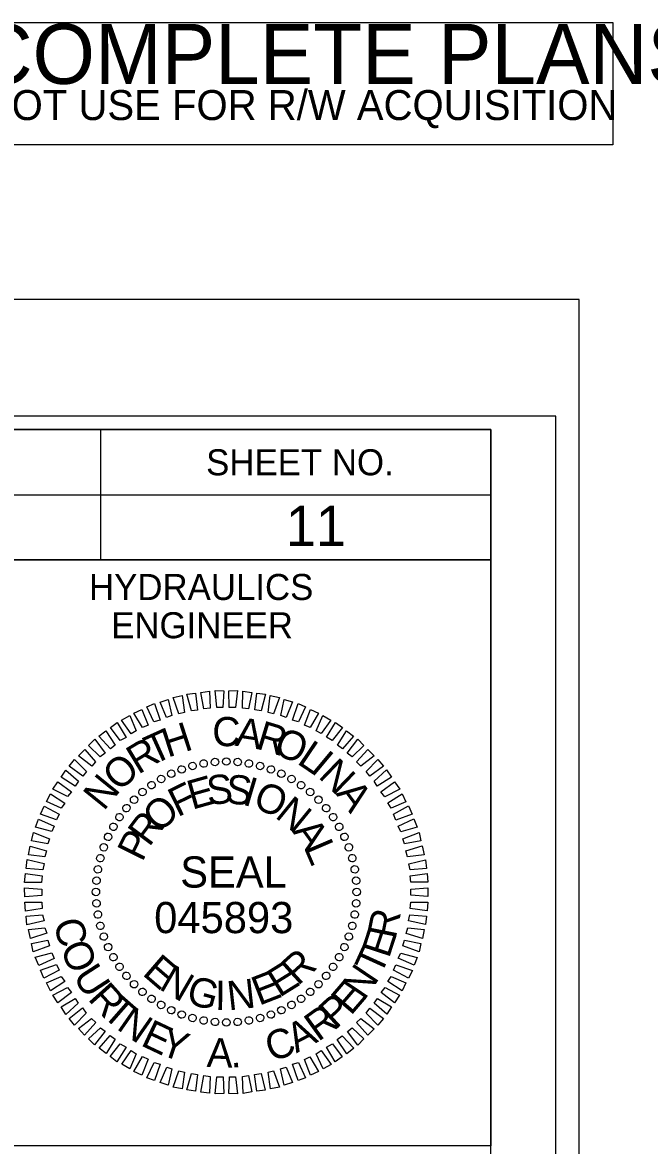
# Model space of a CAD drawing. Extents: x 1621288 to 1629363, y 896995 to 899414.
# Drawn here: x 1628879.4 to 1628999.9, y 897932.1 to 898147.8 of the extents above; entities that cross this region are included whole.
import ezdxf

# ---------------------------------------------------------------- set-up
doc = ezdxf.new("R2010")
doc.units = 0
for name, color, linetype in [('Default', 7, 'Continuous'), ('Exist XS Ground Line', 7, 'Continuous'), ('Prop Plan Preparation Cover Label', 7, 'Continuous'), ('Prop Vertical Profile Curve Label', 7, 'Continuous'), ('Prop Vertical Profile Grade Label', 7, 'Continuous'), ('Sheet Layout Plan Border', 7, 'Continuous'), ('Sheet Layout Profile Border', 7, 'Continuous')]:
    doc.layers.add(name, color=color, linetype=linetype)

msp = doc.modelspace()

# ---------------------------------------------------------------- linework, layer by layer
at = {"layer": 'Default'}
for p, q in [((1628912.06, 898005.01), (1628912.06, 898005.01)), ((1628914.21, 898005.46), (1628914.21, 898005.46)), ((1628916.36, 898005.76), (1628916.36, 898005.76)), ((1628918.56, 898005.91), (1628918.56, 898005.91)), ((1628920.76, 898005.76), (1628920.76, 898005.76)), ((1628922.91, 898005.46), (1628922.91, 898005.46)), ((1628925.06, 898005.01), (1628925.06, 898005.01)), ((1628906.06, 898002.51), (1628906.06, 898002.51)), ((1628908.01, 898003.51), (1628908.01, 898003.51)), ((1628909.96, 898004.36), (1628909.96, 898004.36)), ((1628927.16, 898004.36), (1628927.16, 898004.36)), ((1628929.16, 898003.51), (1628929.16, 898003.51)), ((1628931.11, 898002.51), (1628931.11, 898002.51)), ((1628904.21, 898001.31), (1628904.21, 898001.31)), ((1628932.91, 898001.36), (1628932.91, 898001.36)), ((1628900.81, 897998.51), (1628900.81, 897998.51)), ((1628902.41, 898000.06), (1628902.41, 898000.06)), ((1628934.71, 898000.01), (1628934.71, 898000.01)), ((1628936.26, 897998.56), (1628936.26, 897998.56)), ((1628899.31, 897996.96), (1628899.31, 897996.96)), ((1628937.81, 897996.91), (1628937.81, 897996.91)), ((1628898.01, 897995.16), (1628898.01, 897995.16)), ((1628939.06, 897995.16), (1628939.06, 897995.16)), ((1628896.81, 897993.31), (1628896.81, 897993.31)), ((1628940.26, 897993.31), (1628940.26, 897993.31)), ((1628894.96, 897989.36), (1628894.96, 897989.36)), ((1628895.81, 897991.36), (1628895.81, 897991.36)), ((1628941.26, 897991.36), (1628941.26, 897991.36)), ((1628942.11, 897989.36), (1628942.11, 897989.36)), ((1628894.31, 897987.31), (1628894.31, 897987.31)), ((1628942.76, 897987.31), (1628942.76, 897987.31)), ((1628893.86, 897985.16), (1628893.86, 897985.16)), ((1628943.21, 897985.11), (1628943.21, 897985.11)), ((1628893.56, 897983.01), (1628893.56, 897983.01)), ((1628943.51, 897982.96), (1628943.51, 897982.96)), ((1628893.46, 897980.81), (1628893.46, 897980.81)), ((1628943.66, 897980.76), (1628943.66, 897980.76)), ((1628893.61, 897978.61), (1628893.61, 897978.61)), ((1628943.56, 897978.56), (1628943.56, 897978.56)), ((1628893.91, 897976.46), (1628893.91, 897976.46)), ((1628943.26, 897976.46), (1628943.26, 897976.46)), ((1628894.36, 897974.31), (1628894.36, 897974.31)), ((1628942.76, 897974.26), (1628942.76, 897974.26)), ((1628895.01, 897972.21), (1628895.01, 897972.21)), ((1628942.11, 897972.21), (1628942.11, 897972.21)), ((1628895.86, 897970.21), (1628895.86, 897970.21)), ((1628941.31, 897970.21), (1628941.31, 897970.21)), ((1628896.86, 897968.26), (1628896.86, 897968.26)), ((1628940.31, 897968.26), (1628940.31, 897968.26)), ((1628898.06, 897966.41), (1628898.06, 897966.41)), ((1628939.11, 897966.41), (1628939.11, 897966.41)), ((1628899.31, 897964.66), (1628899.31, 897964.66)), ((1628937.76, 897964.66), (1628937.76, 897964.66)), ((1628900.81, 897963.06), (1628900.81, 897963.06)), ((1628902.41, 897961.56), (1628902.41, 897961.56)), ((1628934.66, 897961.56), (1628934.66, 897961.56)), ((1628936.31, 897963.06), (1628936.31, 897963.06)), ((1628904.16, 897960.26), (1628904.16, 897960.26)), ((1628932.91, 897960.31), (1628932.91, 897960.31)), ((1628906.01, 897959.06), (1628906.01, 897959.06)), ((1628907.96, 897958.06), (1628907.96, 897958.06)), ((1628909.96, 897957.21), (1628909.96, 897957.21)), ((1628927.11, 897957.21), (1628927.11, 897957.21)), ((1628929.11, 897958.06), (1628929.11, 897958.06)), ((1628931.11, 897959.06), (1628931.11, 897959.06)), ((1628912.06, 897956.56), (1628912.06, 897956.56)), ((1628914.21, 897956.11), (1628914.21, 897956.11)), ((1628916.36, 897955.81), (1628916.36, 897955.81)), ((1628918.51, 897955.71), (1628918.51, 897955.71)), ((1628920.71, 897955.86), (1628920.71, 897955.86)), ((1628922.91, 897956.11), (1628922.91, 897956.11)), ((1628925.06, 897956.56), (1628925.06, 897956.56))]:
    msp.add_line(p, q, dxfattribs=at)
for points in [[(1628916.76, 898016.26), (1628916.41, 898019.51), (1628918.06, 898019.46), (1628917.91, 898016.26)], [(1628919.11, 898016.26), (1628919.06, 898019.46), (1628920.71, 898019.51), (1628920.31, 898016.26)], [(1628907.06, 898014.36), (1628905.86, 898017.31), (1628907.41, 898017.81), (1628908.11, 898014.71)], [(1628909.46, 898015.06), (1628908.36, 898018.21), (1628910.06, 898018.56), (1628910.51, 898015.31)], [(1628911.86, 898015.66), (1628911.01, 898018.81), (1628912.66, 898019.01), (1628913.06, 898015.76)], [(1628914.26, 898016.01), (1628913.66, 898019.16), (1628915.31, 898019.41), (1628915.46, 898016.16)], [(1628921.66, 898016.16), (1628921.76, 898019.41), (1628923.46, 898019.16), (1628922.86, 898016.01)], [(1628924.06, 898015.81), (1628924.46, 898019.01), (1628926.11, 898018.81), (1628925.26, 898015.66)], [(1628926.61, 898015.31), (1628927.01, 898018.56), (1628928.76, 898018.21), (1628927.66, 898015.06)], [(1628929.01, 898014.71), (1628929.66, 898017.81), (1628931.26, 898017.36), (1628930.06, 898014.36)], [(1628902.46, 898012.41), (1628900.81, 898015.21), (1628902.36, 898015.91), (1628903.56, 898012.91)], [(1628904.66, 898013.51), (1628903.31, 898016.41), (1628904.76, 898017.01), (1628905.86, 898013.86)], [(1628931.26, 898013.86), (1628932.36, 898017.01), (1628933.81, 898016.41), (1628932.41, 898013.51)], [(1628933.56, 898012.91), (1628934.71, 898015.91), (1628936.31, 898015.21), (1628934.66, 898012.41)], [(1628898.16, 898009.91), (1628896.31, 898012.41), (1628897.61, 898013.41), (1628899.31, 898010.51)], [(1628900.31, 898011.21), (1628898.41, 898013.86), (1628900.01, 898014.71), (1628901.26, 898011.81)], [(1628935.81, 898011.81), (1628937.11, 898014.71), (1628938.66, 898013.86), (1628936.81, 898011.26)], [(1628937.81, 898010.56), (1628939.56, 898013.41), (1628940.86, 898012.41), (1628938.91, 898009.91)], [(1628896.31, 898008.36), (1628894.06, 898010.76), (1628895.41, 898011.81), (1628897.21, 898009.06)], [(1628939.91, 898009.06), (1628941.66, 898011.81), (1628943.01, 898010.76), (1628940.86, 898008.36)], [(1628894.31, 898006.81), (1628892.11, 898008.96), (1628893.31, 898010.16), (1628895.26, 898007.51)], [(1628941.81, 898007.51), (1628943.81, 898010.16), (1628945.01, 898008.96), (1628942.76, 898006.81)], [(1628892.71, 898005.01), (1628890.16, 898007.01), (1628891.36, 898008.21), (1628893.46, 898005.81)], [(1628943.61, 898005.81), (1628945.76, 898008.21), (1628946.96, 898007.01), (1628944.41, 898005.01)], [(1628891.01, 898003.11), (1628888.36, 898005.01), (1628889.41, 898006.31), (1628891.71, 898004.01)], [(1628945.41, 898004.01), (1628947.71, 898006.31), (1628948.76, 898005.01), (1628946.11, 898003.06)], [(1628889.51, 898001.16), (1628886.81, 898002.86), (1628887.71, 898004.26), (1628890.16, 898002.11)], [(1628946.96, 898002.11), (1628949.36, 898004.31), (1628950.31, 898002.86), (1628947.56, 898001.16)], [(1628888.06, 897999.16), (1628885.26, 898000.56), (1628886.21, 898002.01), (1628888.81, 898000.06)], [(1628948.26, 898000.06), (1628950.91, 898002.01), (1628951.91, 898000.56), (1628949.01, 897999.11)], [(1628886.86, 897996.96), (1628884.01, 897998.21), (1628884.76, 897999.71), (1628887.51, 897997.91)], [(1628949.61, 897997.96), (1628952.36, 897999.71), (1628953.06, 897998.16), (1628950.21, 897996.96)], [(1628885.96, 897994.71), (1628882.86, 897995.81), (1628883.56, 897997.31), (1628886.46, 897995.76)], [(1628950.66, 897995.81), (1628953.56, 897997.36), (1628954.26, 897995.76), (1628951.16, 897994.66)], [(1628885.01, 897992.46), (1628881.91, 897993.31), (1628882.46, 897994.81), (1628885.51, 897993.46)], [(1628951.61, 897993.51), (1628954.61, 897994.86), (1628955.21, 897993.26), (1628952.11, 897992.41)], [(1628884.26, 897990.06), (1628881.16, 897990.66), (1628881.51, 897992.26), (1628884.61, 897991.06)], [(1628952.46, 897991.06), (1628955.61, 897992.26), (1628955.96, 897990.66), (1628952.81, 897990.06)], [(1628883.71, 897987.61), (1628880.56, 897987.96), (1628880.86, 897989.66), (1628884.01, 897988.71)], [(1628953.06, 897988.71), (1628956.21, 897989.71), (1628956.56, 897987.96), (1628953.41, 897987.61)], [(1628883.31, 897985.11), (1628880.11, 897985.36), (1628880.31, 897987.06), (1628883.56, 897986.31)], [(1628953.61, 897986.26), (1628956.81, 897987.01), (1628957.01, 897985.36), (1628953.86, 897985.11)], [(1628883.06, 897982.66), (1628879.81, 897982.66), (1628879.96, 897984.36), (1628883.16, 897983.91)], [(1628953.91, 897983.91), (1628957.16, 897984.41), (1628957.26, 897982.71), (1628954.01, 897982.71)], [(1628883.11, 897980.16), (1628879.86, 897979.91), (1628879.81, 897981.61), (1628883.11, 897981.36)], [(1628954.01, 897981.41), (1628957.26, 897981.66), (1628957.26, 897979.96), (1628954.01, 897980.21)], [(1628883.16, 897977.66), (1628879.96, 897977.16), (1628879.86, 897978.91), (1628883.11, 897978.86)], [(1628954.01, 897978.91), (1628957.26, 897978.91), (1628957.16, 897977.21), (1628953.91, 897977.66)], [(1628883.56, 897975.31), (1628880.26, 897974.51), (1628880.11, 897976.21), (1628883.26, 897976.46)], [(1628953.81, 897976.46), (1628957.01, 897976.21), (1628956.81, 897974.56), (1628953.56, 897975.31)], [(1628884.06, 897972.91), (1628880.91, 897971.91), (1628880.56, 897973.61), (1628883.71, 897973.96)], [(1628953.46, 897973.96), (1628956.56, 897973.61), (1628956.26, 897971.91), (1628953.11, 897972.86)], [(1628884.61, 897970.51), (1628881.46, 897969.31), (1628881.16, 897970.96), (1628884.26, 897971.56)], [(1628952.81, 897971.56), (1628955.96, 897970.96), (1628955.61, 897969.31), (1628952.46, 897970.51)], [(1628885.51, 897968.06), (1628882.51, 897966.71), (1628881.86, 897968.31), (1628885.01, 897969.16)], [(1628952.11, 897969.11), (1628955.21, 897968.26), (1628954.66, 897966.76), (1628951.61, 897968.11)], [(1628886.46, 897965.81), (1628883.51, 897964.26), (1628882.86, 897965.81), (1628885.96, 897966.91)], [(1628951.16, 897966.86), (1628954.31, 897965.76), (1628953.56, 897964.26), (1628950.66, 897965.81)], [(1628887.51, 897963.66), (1628884.76, 897961.86), (1628884.01, 897963.41), (1628886.86, 897964.61)], [(1628950.26, 897964.61), (1628953.06, 897963.41), (1628952.36, 897961.86), (1628949.61, 897963.66)], [(1628888.81, 897961.56), (1628886.21, 897959.56), (1628885.26, 897961.01), (1628888.06, 897962.46)], [(1628949.06, 897962.46), (1628951.86, 897961.01), (1628950.91, 897959.56), (1628948.31, 897961.56)], [(1628890.11, 897959.46), (1628887.71, 897957.31), (1628886.81, 897958.76), (1628889.51, 897960.41)], [(1628947.61, 897960.41), (1628950.31, 897958.76), (1628949.41, 897957.36), (1628946.96, 897959.46)], [(1628891.66, 897957.56), (1628889.41, 897955.26), (1628888.36, 897956.56), (1628890.96, 897958.56)], [(1628946.11, 897958.51), (1628948.76, 897956.56), (1628947.71, 897955.26), (1628945.41, 897957.56)], [(1628893.51, 897955.76), (1628891.31, 897953.36), (1628890.16, 897954.61), (1628892.66, 897956.56)], [(1628944.41, 897956.56), (1628946.96, 897954.56), (1628945.76, 897953.36), (1628943.61, 897955.76)], [(1628895.31, 897954.11), (1628893.26, 897951.46), (1628892.11, 897952.66), (1628894.36, 897954.76)], [(1628897.21, 897952.56), (1628895.46, 897949.81), (1628894.11, 897950.81), (1628896.26, 897953.26)], [(1628940.81, 897953.21), (1628943.06, 897950.81), (1628941.71, 897949.76), (1628939.86, 897952.51)], [(1628942.76, 897954.76), (1628945.01, 897952.61), (1628943.81, 897951.41), (1628941.86, 897954.06)], [(1628899.31, 897951.06), (1628897.56, 897948.21), (1628896.26, 897949.21), (1628898.16, 897951.66)], [(1628938.96, 897951.66), (1628940.81, 897949.16), (1628939.51, 897948.21), (1628937.81, 897951.06)], [(1628901.26, 897949.76), (1628900.01, 897946.86), (1628898.46, 897947.76), (1628900.31, 897950.36)], [(1628903.56, 897948.71), (1628902.36, 897945.66), (1628900.81, 897946.36), (1628902.46, 897949.21)], [(1628934.61, 897949.16), (1628936.31, 897946.36), (1628934.76, 897945.66), (1628933.56, 897948.66)], [(1628936.76, 897950.36), (1628938.71, 897947.71), (1628937.16, 897946.86), (1628935.86, 897949.76)], [(1628905.86, 897947.76), (1628904.76, 897944.61), (1628903.31, 897945.16), (1628904.71, 897948.11)], [(1628908.11, 897946.86), (1628907.41, 897943.76), (1628905.86, 897944.26), (1628907.11, 897947.21)], [(1628910.51, 897946.26), (1628910.06, 897943.06), (1628908.36, 897943.36), (1628909.46, 897946.51)], [(1628927.66, 897946.51), (1628928.76, 897943.36), (1628927.06, 897943.01), (1628926.61, 897946.26)], [(1628930.06, 897947.21), (1628931.26, 897944.26), (1628929.66, 897943.76), (1628928.96, 897946.86)], [(1628932.41, 897948.11), (1628933.76, 897945.16), (1628932.36, 897944.61), (1628931.26, 897947.76)], [(1628913.06, 897945.81), (1628912.66, 897942.56), (1628911.01, 897942.81), (1628911.86, 897945.96)], [(1628915.46, 897945.41), (1628915.31, 897942.21), (1628913.66, 897942.41), (1628914.26, 897945.56)], [(1628917.96, 897945.36), (1628918.06, 897942.11), (1628916.41, 897942.06), (1628916.76, 897945.31)], [(1628920.36, 897945.31), (1628920.71, 897942.06), (1628919.06, 897942.11), (1628919.16, 897945.36)], [(1628922.81, 897945.56), (1628923.46, 897942.46), (1628921.81, 897942.16), (1628921.66, 897945.41)], [(1628925.26, 897945.96), (1628926.06, 897942.76), (1628924.41, 897942.61), (1628924.01, 897945.76)]]:
    msp.add_lwpolyline(points, close=True, dxfattribs=at)
for centre, major_axis in [((1628916.38, 898005.8), (-0.063, 0.717)), ((1628918.57, 898005.89), (0, 0.719)), ((1628920.75, 898005.8), (0.063, 0.717)), ((1628910, 898004.38), (-0.246, 0.676)), ((1628912.08, 898005.04), (-0.186, 0.695)), ((1628914.21, 898005.51), (-0.125, 0.708)), ((1628922.92, 898005.51), (0.125, 0.708)), ((1628925.05, 898005.04), (0.186, 0.695)), ((1628927.13, 898004.38), (0.246, 0.676)), ((1628906.04, 898002.54), (-0.36, 0.623)), ((1628907.98, 898003.55), (-0.304, 0.652)), ((1628929.15, 898003.55), (0.304, 0.652)), ((1628931.09, 898002.54), (0.36, 0.623)), ((1628902.46, 898000.03), (-0.462, 0.551)), ((1628904.19, 898001.36), (-0.413, 0.589)), ((1628932.94, 898001.36), (0.413, 0.589)), ((1628934.67, 898000.03), (0.462, 0.551)), ((1628900.85, 897998.56), (-0.509, 0.509)), ((1628936.28, 897998.56), (0.509, 0.509)), ((1628898.04, 897995.21), (-0.589, 0.413)), ((1628899.37, 897996.94), (-0.551, 0.462)), ((1628937.76, 897996.94), (0.551, 0.462)), ((1628939.09, 897995.21), (0.589, 0.413)), ((1628896.87, 897993.37), (-0.623, 0.36)), ((1628940.26, 897993.37), (0.623, 0.36)), ((1628895.86, 897991.43), (-0.652, 0.304)), ((1628941.27, 897991.43), (0.652, 0.304)), ((1628895.02, 897989.41), (-0.676, 0.246)), ((1628942.11, 897989.41), (0.676, 0.246)), ((1628894.36, 897987.32), (-0.695, 0.186)), ((1628942.77, 897987.32), (0.695, 0.186)), ((1628893.89, 897985.19), (-0.708, 0.125)), ((1628943.24, 897985.19), (0.708, 0.125)), ((1628893.61, 897983.02), (-0.717, 0.063)), ((1628943.52, 897983.02), (0.717, 0.063)), ((1628893.51, 897980.84), (-0.719, 0)), ((1628943.62, 897980.84), (0.719, 0)), ((1628893.61, 897978.65), (-0.717, -0.063)), ((1628943.52, 897978.65), (0.717, -0.063)), ((1628893.89, 897976.49), (-0.708, -0.125)), ((1628943.24, 897976.49), (0.708, -0.125)), ((1628894.36, 897974.35), (-0.695, -0.186)), ((1628942.77, 897974.35), (0.695, -0.186)), ((1628895.02, 897972.27), (-0.676, -0.246)), ((1628942.11, 897972.27), (0.676, -0.246)), ((1628895.86, 897970.25), (-0.652, -0.304)), ((1628941.27, 897970.25), (0.652, -0.304)), ((1628896.87, 897968.31), (-0.623, -0.36)), ((1628940.26, 897968.31), (0.623, -0.36)), ((1628898.04, 897966.47), (-0.589, -0.413)), ((1628939.09, 897966.47), (0.589, -0.413)), ((1628899.37, 897964.73), (-0.551, -0.462)), ((1628900.85, 897963.12), (-0.509, -0.509)), ((1628936.28, 897963.12), (0.509, -0.509)), ((1628937.76, 897964.73), (0.551, -0.462)), ((1628902.46, 897961.65), (-0.462, -0.551)), ((1628934.67, 897961.65), (0.462, -0.551)), ((1628904.19, 897960.31), (-0.413, -0.589)), ((1628906.04, 897959.14), (-0.36, -0.623)), ((1628931.09, 897959.14), (0.36, -0.623)), ((1628932.94, 897960.31), (0.413, -0.589)), ((1628907.98, 897958.13), (-0.304, -0.652)), ((1628910, 897957.29), (-0.246, -0.676)), ((1628912.08, 897956.64), (-0.186, -0.695)), ((1628914.21, 897956.16), (-0.125, -0.708)), ((1628922.92, 897956.16), (0.125, -0.708)), ((1628925.05, 897956.64), (0.186, -0.695)), ((1628927.13, 897957.29), (0.246, -0.676)), ((1628929.15, 897958.13), (0.304, -0.652)), ((1628916.38, 897955.88), (-0.063, -0.717)), ((1628918.57, 897955.78), (0, -0.719)), ((1628920.75, 897955.88), (0.063, -0.717))]:
    msp.add_ellipse(centre, major_axis=major_axis, ratio=0.999708, dxfattribs=at)
at = {"layer": 'Exist XS Ground Line'}
for p, q in [((1628894.38, 898069.61), (1628894.38, 898044.61)), ((1628769.33, 898057.11), (1628969.38, 898057.11))]:
    msp.add_line(p, q, dxfattribs=at)
for points in [[(1628969.38, 898069.66), (1627469.38, 898069.66), (1627469.38, 897019.66), (1628969.38, 897019.66)], [(1628769.33, 898069.66), (1628969.38, 898069.66), (1628969.38, 898044.61), (1628769.33, 898044.61)], [(1628869.38, 898044.61), (1628969.38, 898044.61), (1628969.38, 897932.11), (1628869.38, 897932.11)]]:
    msp.add_lwpolyline(points, close=True, dxfattribs=at)
at = {"layer": 'Prop Plan Preparation Cover Label'}
msp.add_lwpolyline([(1628845.86, 898124.35), (1628845.86, 898147.85), (1628992.86, 898147.85), (1628992.86, 898124.35)], close=True, dxfattribs=at)
at = {"layer": 'Prop Vertical Profile Curve Label'}
msp.add_lwpolyline([(1627315.38, 897017.11), (1628981.88, 897017.11), (1628981.88, 898072.21), (1627315.38, 898072.21)], close=True, dxfattribs=at)
at = {"layer": 'Sheet Layout Plan Border'}
msp.add_lwpolyline([(1627302.38, 896994.66), (1628986.38, 896994.66), (1628986.38, 898094.66), (1627302.38, 898094.66)], close=True, dxfattribs=at)
at = {"layer": 'Sheet Layout Profile Border'}
msp.add_line((1628986.38, 898094.66), (1627302.38, 898094.66), dxfattribs=at)

# ---------------------------------------------------------------- texts
at = {"layer": 'Default'}
for s, height, rotation, p in [('H', 5.6, 17.9268, (1628907.29, 898006.62)), ('C', 5.6, 359.8514, (1628915.86, 898008.85)), ('A', 5.6, 351.2223, (1628920.1, 898008.95)), ('R', 5.6, 343.1874, (1628924.03, 898008.46)), ('T', 5.6, 24.3275, (1628904.48, 898005.2)), ('O', 5.6, 336.242, (1628927.33, 898007.6)), ('R', 5.6, 31.2729, (1628901.63, 898003.31)), ('L', 5.6, 326.0282, (1628931.95, 898005.62)), ('O', 5.6, 41.4867, (1628897.91, 897999.95)), ('I', 5.6, 320.0485, (1628934.46, 898004.1)), ('N', 5.6, 316.0496, (1628936.05, 898002.93)), ('N', 5.6, 51.032, (1628895.02, 897996.25)), ('E', 5.6, 15.6529, (1628911.99, 897996.61)), ('S', 5.6, 5.0487, (1628915.01, 897997.55)), ('S', 5.6, 354.1866, (1628918.24, 897997.93)), ('I', 5.6, 343.3245, (1628921.47, 897997.69)), ('F', 5.6, 26.1465, (1628909.22, 897995.14)), ('O', 5.6, 336.6634, (1628923.41, 897997.24)), ('A', 5.6, 306.5043, (1628939.48, 897999.73)), ('O', 5.6, 42.0574, (1628905.64, 897992.02)), ('N', 5.6, 320.7526, (1628927.74, 897995.29)), ('R', 5.6, 53.1038, (1628903.73, 897989.33)), ('A', 5.6, 305.8367, (1628931.16, 897992.45)), ('P', 5.6, 63.7079, (1628902.41, 897986.45)), ('L', 5.6, 293.1688, (1628933.41, 897989.41)), ('SEAL', 5.992, 360, (1628909.71, 897981.68)), ('045893', 5.994, 360, (1628904.7, 897972.93)), ('R', 5.6, 78.5969, (1628951.09, 897971.65)), ('C', 5.6, 284.0401, (1628885.33, 897975.08)), ('E', 5.6, 71.9487, (1628949.81, 897967.95)), ('O', 5.6, 292.6692, (1628886.56, 897970.15)), ('T', 5.6, 65.548, (1628948.18, 897964.55)), ('E', 5.6, 319.2324, (1628902.24, 897965.03)), ('R', 5.6, 42.4535, (1628932.31, 897962.69)), ('U', 5.6, 302.883, (1628888.95, 897964.64)), ('N', 5.6, 329.8366, (1628905.42, 897962.29)), ('E', 5.6, 21.2452, (1628924.84, 897958.95)), ('E', 5.6, 31.8494, (1628928.75, 897960.47)), ('N', 5.6, 56.0027, (1628945.08, 897959.87)), ('R', 5.6, 311.7969, (1628891.81, 897960.24)), ('G', 5.6, 344.7525, (1628910.63, 897959.52)), ('I', 5.6, 359.6683, (1628916.37, 897958.19)), ('N', 5.6, 6.3293, (1628919.01, 897958.08)), ('E', 5.6, 49.3544, (1628942.48, 897956.94)), ('T', 5.6, 318.7423, (1628894.49, 897957.16)), ('P', 5.6, 42.7062, (1628939.56, 897954.34)), ('N', 5.6, 325.143, (1628897.28, 897954.62)), ('R', 5.6, 35.7608, (1628936.21, 897951.99)), ('E', 5.6, 334.6883, (1628901.91, 897951.45)), ('Y', 5.6, 341.3366, (1628905.42, 897949.71)), ('A', 5.6, 27.7259, (1628932.01, 897949.82)), ('A', 5.6, 357.753, (1628914.74, 897947.26)), ('C', 5.6, 19.0968, (1628927.21, 897948.15)), ('.', 5.6, 5.7878, (1628919.47, 897947.05))]:
    msp.add_text(s, height=height, rotation=rotation, dxfattribs=at).set_placement(p)
at = {"layer": 'Exist XS Ground Line'}
for s, p in [('SHEET NO.', (1628914.69, 898060.87)), ('HYDRAULICS', (1628892.19, 898036.92)), ('ENGINEER', (1628896.44, 898029.57))]:
    msp.add_text(s, height=5, dxfattribs=at).set_placement(p)
at = {"layer": 'Prop Plan Preparation Cover Label'}
for s, height, p in [('INCOMPLETE PLANS', 11.52, (1628854.81, 898136.05)), ('DO NOT USE FOR R/W ACQUISITION', 5.76, (1628858.06, 898129.1))]:
    msp.add_text(s, height=height, dxfattribs=at).set_placement(p)
at = {"layer": 'Prop Vertical Profile Grade Label'}
msp.add_text('11', height=7.75, dxfattribs=at).set_placement((1628930, 898047.27))

doc.saveas('drawing.dxf')
